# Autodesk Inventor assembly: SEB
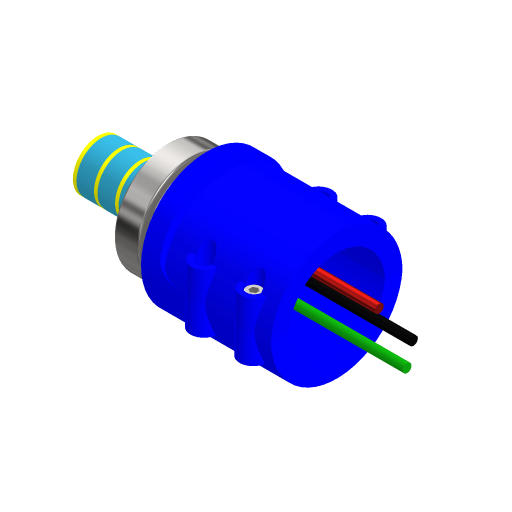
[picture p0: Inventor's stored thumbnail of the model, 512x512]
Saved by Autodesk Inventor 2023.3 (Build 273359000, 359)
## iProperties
Created: 2023-11
Part Number: SEB
Document SubType Name: Assembly
Designer: Thier
Author: Thier
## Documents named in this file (13)
- E:\Dossier technique\Eolienne\Albra\Maquette Numerique Eolienne\214112232-CEB-Eolienne\SEB.iam
- E:\Dossier technique\Eolienne\Albra\Maquette Numerique Eolienne\214112232-CEB-Eolienne\04-Corps de Pivot.ipt
- E:\Dossier technique\Eolienne\Albra\Maquette Numerique Eolienne\214112232-CEB-Eolienne\02-DIN 625 SKF - SKF 6007-2Z.ipt
- E:\Dossier technique\Eolienne\Albra\Maquette Numerique Eolienne\214112232-CEB-Eolienne\05-NF E 22-165 - 35x1,75.ipt
- E:\Dossier technique\Eolienne\Albra\Maquette Numerique Eolienne\214112232-CEB-Eolienne\Disque collecteur\20n-Disque collecteur Neutre.iam
- E:\Dossier technique\Eolienne\Albra\Maquette Numerique Eolienne\214112232-CEB-Eolienne\Disque collecteur\20t-Disque collecteur Phase.iam
- E:\Dossier technique\Eolienne\Albra\Maquette Numerique Eolienne\214112232-CEB-Eolienne\Disque collecteur\20t-Disque collecteur Terre.iam
- E:\Dossier technique\Eolienne\Albra\Maquette Numerique Eolienne\214112232-CEB-Eolienne\Disque collecteur\23-Disque collecteur.ipt
- E:\Dossier technique\Eolienne\Albra\Maquette Numerique Eolienne\214112232-CEB-Eolienne\19-Tube isolant.ipt
- E:\Dossier technique\Eolienne\Albra\Maquette Numerique Eolienne\214112232-CEB-Eolienne\25-NF E 25-130 - M6 x 55A.ipt
- E:\Dossier technique\Eolienne\Albra\Maquette Numerique Eolienne\214112232-CEB-Eolienne\06-MachoireDePivot.ipt
- E:\Dossier technique\Eolienne\Albra\Maquette Numerique Eolienne\214112232-CEB-Eolienne\26-ISO 4032 - M5NF EN.ipt
- E:\Dossier technique\Eolienne\Albra\Maquette Numerique Eolienne\214112232-CEB-Eolienne\27-NF E 25-125 - M5 x 30.ipt
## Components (21 placed, 12 different names)
1. 04-Corps de Pivot:1
2. DIN 625 SKF- avec deux flasques Z SKF 6007-2Z:1 — Placage:2
3. NF E 22-165 35x1,75:1 — Logement:1
4. 20n-Disque collecteur Neutre:1 [sub-assembly] — Logement:4, Logement:27, Logement:28, Logement:29
5. 20t-Disque collecteur Phase:1 [sub-assembly] — Logement:3, Logement:10, Placage:3, Logement:25, Logement:26
6. 20t-Disque collecteur Terre:1 [sub-assembly] — Logement:12, Logement:30
7. 23-Disque collecteur:1 — Logement:4, Logement:10, Logement:26, Logement:27
8. 23-Disque collecteur:2 — Logement:3, Logement:13, Logement:14, Logement:25
9. 23-Disque collecteur:3 — Logement:28, Logement:29, Logement:30
10. 19-Tube isolant:1 — Logement:13
11. NF E 25-130 - A M6 x 55:1 — Logement:14
12. 06-MachoireDePivot:1 — Logement:15, Logement:16, Logement:17, Logement:18, Logement:19, Logement:20
13. NF E 25-125 M5 x 30:4 — Logement:20
14. NF E 25-125 M5 x 30:3 — Logement:19
15. NF E 25-125 M5 x 30:2 — Logement:18
16. NF E 25-125 M5 x 30:1 — Logement:17
17. NF EN 24032 M5:1 — Logement:22
18. NF EN 24032 M5:2
19. NF EN 24032 M5:4 — Angle:1, Logement:21
20. NF EN 24032 M5:5 — Logement:24
21. NF EN 24032 M5:6 — Logement:23
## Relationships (26: Insert 23, Mate 2, Angle 1)
- Placage:2 [Mate]: DIN 625 SKF- avec deux flasques Z SKF 6007-2Z:1
- Logement:1 [Insert]: NF E 22-165 35x1,75:1
- Logement:3 [Insert]: 20t-Disque collecteur Phase:1 ↔ 23-Disque collecteur:2
- Logement:4 [Insert]: 20n-Disque collecteur Neutre:1 ↔ 23-Disque collecteur:1
- Logement:10 [Insert]: 20t-Disque collecteur Phase:1 ↔ 23-Disque collecteur:1
- Logement:12 [Insert]: 20t-Disque collecteur Terre:1
- Placage:3 [Mate]: 20t-Disque collecteur Phase:1
- Logement:13 [Insert]: 23-Disque collecteur:2 ↔ 19-Tube isolant:1
- Logement:14 [Insert]: 23-Disque collecteur:2 ↔ NF E 25-130 - A M6 x 55:1
- Logement:15 [Insert]: 06-MachoireDePivot:1
- Logement:16 [Insert]: 06-MachoireDePivot:1
- Logement:17 [Insert]: 06-MachoireDePivot:1 ↔ NF E 25-125 M5 x 30:1
- Logement:18 [Insert]: 06-MachoireDePivot:1 ↔ NF E 25-125 M5 x 30:2
- Logement:19 [Insert]: 06-MachoireDePivot:1 ↔ NF E 25-125 M5 x 30:3
- Logement:20 [Insert]: 06-MachoireDePivot:1 ↔ NF E 25-125 M5 x 30:4
- Angle:1: NF EN 24032 M5:4
- Logement:21 [Insert]: NF EN 24032 M5:4
- Logement:22 [Insert]: NF EN 24032 M5:1
- Logement:23 [Insert]: NF EN 24032 M5:6
- Logement:24 [Insert]: NF EN 24032 M5:5
- Logement:25 [Insert]: 20t-Disque collecteur Phase:1 ↔ 23-Disque collecteur:2
- Logement:26 [Insert]: 20t-Disque collecteur Phase:1 ↔ 23-Disque collecteur:1
- Logement:27 [Insert]: 20n-Disque collecteur Neutre:1 ↔ 23-Disque collecteur:1
- Logement:28 [Insert]: 20n-Disque collecteur Neutre:1 ↔ 23-Disque collecteur:3
- Logement:29 [Insert]: 20n-Disque collecteur Neutre:1 ↔ 23-Disque collecteur:3
- Logement:30 [Insert]: 20t-Disque collecteur Terre:1 ↔ 23-Disque collecteur:3
